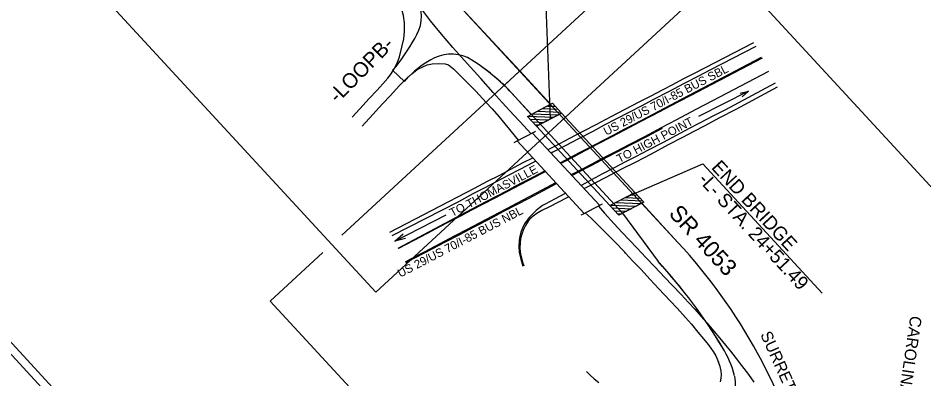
# Model space of a CAD drawing. Extents: x 1695041 to 1706254, y 786537 to 798223.
# Drawn here: x 1702539 to 1704183, y 794568 to 795222 of the extents above; entities that cross this region are included whole.
import ezdxf

# ---------------------------------------------------------------- set-up
doc = ezdxf.new("R2010")
doc.units = 0
for name, color, linetype in [('Default', 7, 'Continuous'), ('Old_Level_3', 7, 'Continuous'), ('Old_Level_4', 7, 'Continuous'), ('Old_Level_47', 7, 'Continuous'), ('Prop Approach Slab', 7, 'Continuous'), ('Prop EOT', 7, 'Continuous'), ('Prop Roadway Bridge', 7, 'Continuous'), ('Sheet Data Field CELL', 7, 'Continuous'), ('Sheet Title CELL', 7, 'Continuous')]:
    doc.layers.add(name, color=color, linetype=linetype)

msp = doc.modelspace()

# ---------------------------------------------------------------- linework, layer by layer
at = {"layer": 'Default'}
for p, q in [((1703449.8, 795126.4), (1703259.9, 795332.1)), ((1703225.7, 795134.5), (1703218.7, 795127.9)), ((1703218.7, 795127.9), (1703240.5, 795107.5)), ((1703421.5, 795100.2), (1703449.8, 795126.4)), ((1703449.8, 795126.4), (1703421.5, 795100.2)), ((1703505.8, 795065.8), (1703449.8, 795126.4)), ((1703240.5, 795107.5), (1703248.1, 795115.5)), ((1703435.6, 795085.8), (1703470.9, 795047.5)), ((1703865.4, 795089.6), (1703774.5, 795043.5)), ((1703505.8, 795065.8), (1703505.8, 795065.8)), ((1703470.9, 795047.5), (1703470.9, 795047.5)), ((1703470.9, 795047.5), (1703470.9, 795047.5)), ((1703671.5, 794886.3), (1703636.6, 794868)), ((1703671.5, 794886.3), (1703671.5, 794886.3)), ((1703671.5, 794886.3), (1703671.5, 794886.3)), ((1703671.5, 794886.3), (1703671.5, 794886.3)), ((1703671.5, 794886.3), (1703671.5, 794886.3)), ((1703671.5, 794886.3), (1703671.5, 794886.3)), ((1703223.4, 794817.6), (1703316.4, 794865)), ((1703636.6, 794868), (1703636.6, 794868)), ((1703636.6, 794868), (1703636.6, 794868)), ((1703636.6, 794868), (1703636.6, 794868)), ((1703636.6, 794868), (1703636.6, 794868)), ((1703636.6, 794868), (1703636.6, 794868)), ((1703636.6, 794868), (1703701.1, 794780.4))]:
    msp.add_line(p, q, dxfattribs=at)
for points in [[(1702347.2, 796012.7), (1702159.6, 795839.5), (1703188.6, 794724.8), (1703925.1, 795404.6), (1702896.1, 796519.3), (1702395.5, 796057.2)], [(1703666.7, 795326.6), (1703127, 794828.4)], [(1704247.3, 793859.6), (1704746.6, 794320.4), (1703838.4, 795304.4)], [(1703850.1, 795086.1), (1703865.4, 795089.6), (1703853.5, 795079.3)], [(1703470.9, 795047.5), (1703488.5, 795056.8), (1703505.8, 795065.8)], [(1703737.1, 794815.1), (1703671.5, 794886.3), (1703671.5, 794886.3)], [(1703242.6, 794822.1), (1703223.4, 794817.6), (1703238.3, 794830.5)], [(1703092.7, 794796.8), (1702997.1, 794708.5), (1703792.4, 793846.8)]]:
    msp.add_lwpolyline(points, dxfattribs=at)
for centre, radius, start, end in [((1703201.5, 795225.4), 70, 332.0106, 28.6224), ((1702910.1, 795380.3), 400, 322.0902, 332.0106), ((1703325.6, 795087), 70, 57.7993, 115.717), ((1703364.7, 795005.9), 160, 115.717, 136.7565), ((1703171.1, 794841.6), 360, 45.9217, 57.7993), ((1703171.1, 794841.6), 360, 42.7091, 45.9217), ((1702989.1, 794124.6), 1018, 14.7589, 42.7091), ((1702989.1, 794124.6), 968, 31.1029, 42.644), ((1703646.7, 794521.4), 200, 14.8969, 31.1029), ((1703791.7, 794559.9), 50, 277.9887, 14.8969)]:
    msp.add_arc(centre, radius, start, end, dxfattribs=at)
at = {"layer": 'Old_Level_3'}
for points in [[(1703145.6, 795042.7), (1703159.4, 795057.7), (1703176.4, 795076.1), (1703190.4, 795091.1), (1703201.5, 795103.1), (1703210.6, 795113.4), (1703216.4, 795121.4), (1703222, 795130.2), (1703227.5, 795140.7), (1703231.4, 795152.1), (1703236.1, 795169.3), (1703239.6, 795184.4), (1703240.7, 795197.8), (1703240.8, 795213.5), (1703238.9, 795226.9), (1703235.9, 795237.7), (1703230.6, 795251.2), (1703223.9, 795265.8), (1703215.6, 795279.8), (1703203.6, 795298.5), (1703197.6, 795306.6)], [(1703418.2, 795069.3), (1703401.7, 795087.5), (1703379, 795112.6), (1703354.2, 795139.9), (1703328.7, 795168.8), (1703308, 795193), (1703288.1, 795217.4), (1703271.7, 795238.9)], [(1703641.3, 795056.9), (1703666.7, 795070.3), (1703688.3, 795081.2), (1703708.9, 795091.9), (1703727.9, 795102), (1703746.4, 795111.8), (1703764.4, 795120.9), (1703786.8, 795132.8), (1703874.8, 795177.9)], [(1703878.3, 795171), (1703796.3, 795128.6), (1703774.5, 795117.1), (1703748.6, 795103.5), (1703720.1, 795088.7), (1703691.4, 795073.7), (1703670.1, 795062.4), (1703649.1, 795051.6), (1703624.3, 795038.9)], [(1703163.8, 795025.9), (1703183.4, 795047.6), (1703201, 795066.7), (1703215, 795081.9), (1703231.1, 795099.2), (1703243.7, 795111.8), (1703254, 795121.4), (1703264, 795128.9), (1703273.7, 795134.1), (1703281.8, 795137.4), (1703290.8, 795139.5), (1703302.6, 795139.6), (1703314.3, 795139.5), (1703320.8, 795137.4), (1703329.8, 795130.2), (1703351.4, 795108.4), (1703369.9, 795089.4), (1703388.8, 795069.2), (1703399.7, 795057.6)], [(1703889.7, 795149.3), (1703812.6, 795109.1), (1703784.4, 795094.5), (1703761.4, 795082.3), (1703736.8, 795069.6), (1703713.8, 795057.6), (1703690.6, 795045.5), (1703666.3, 795032.6), (1703639.9, 795018.9)], [(1703657.6, 795030.1), (1703681.7, 795042.7), (1703702.3, 795053.4), (1703723.9, 795064.8), (1703744.8, 795075.7), (1703768.9, 795088.3), (1703795.5, 795102.3), (1703888.7, 795151.1)], [(1703553.8, 794943.6), (1703580.2, 794957.3), (1703601.6, 794968.7), (1703625.3, 794980.9), (1703649.6, 794993.3), (1703676.8, 795007.7), (1703707.5, 795023.6), (1703735.3, 795038.4), (1703770, 795057), (1703800.1, 795072.9), (1703901.8, 795126.2)], [(1703917.4, 795097), (1703842.2, 795056.7), (1703811.3, 795040.6), (1703785.7, 795027), (1703765.6, 795016.7), (1703745.2, 795005.7), (1703719, 794992.1), (1703688.3, 794975.5), (1703660.8, 794960.9), (1703634.4, 794948.1)], [(1703913.6, 795104.1), (1703821.9, 795055.4), (1703801.4, 795044.9), (1703775.9, 795031.5), (1703757.6, 795021.8), (1703733.6, 795009.3), (1703710.1, 794996.8), (1703682.9, 794982.6)], [(1703399.7, 795057.6), (1703412, 795043.8), (1703423, 795030.3), (1703431.4, 795020), (1703439.3, 795010.5), (1703447.2, 795001)], [(1703418.2, 795069.3), (1703438.9, 795046.4), (1703449.8, 795034.7), (1703464.1, 795019.5), (1703470.3, 795012.7)], [(1703501.5, 794983.8), (1703514.6, 794990.7), (1703539.7, 795003.6), (1703566, 795017.5), (1703588.8, 795029.4), (1703616.1, 795043.6), (1703641.3, 795056.9)], [(1703624.3, 795038.9), (1703603, 795027.7), (1703582.4, 795016.7), (1703556.3, 795003), (1703532.1, 794990.5), (1703509.9, 794978.7), (1703507.2, 794977.3)], [(1703523.1, 794959.7), (1703533.6, 794965.2), (1703558.3, 794978.2), (1703576.3, 794987.5), (1703601.7, 795000.9), (1703621.7, 795011.2), (1703639.2, 795020.8), (1703657.6, 795030.1)], [(1703639.9, 795018.9), (1703616.1, 795006.3), (1703592.5, 794994.1), (1703568, 794981.2), (1703547.9, 794970.6), (1703526.7, 794959.8), (1703524.1, 794958.5)], [(1703544.8, 794936.7), (1703553.5, 794941.3), (1703580.5, 794955.6), (1703606.6, 794969.1), (1703627, 794979.6), (1703654.7, 794994.2), (1703680.4, 795007.6), (1703709.1, 795022.8)], [(1703682.9, 794982.6), (1703659.8, 794970.5), (1703641.8, 794961.2), (1703621.4, 794950.4), (1703600.4, 794939.5), (1703580.4, 794929), (1703562.3, 794919.2), (1703561.5, 794918.8)], [(1703214.3, 794834.1), (1703367.7, 794913.7), (1703391.2, 794926.1), (1703412.4, 794936.9), (1703432.7, 794947.8), (1703456.1, 794960.1), (1703473.4, 794968.9)], [(1703474.4, 794960.4), (1703450.3, 794947.8), (1703429, 794936.5), (1703407.2, 794925.2), (1703385.6, 794913.9), (1703364.9, 794903.2), (1703338.5, 794889.1), (1703217.9, 794827.1)], [(1703479.1, 794962.8), (1703474.4, 794960.4)], [(1703229.3, 794805), (1703342.8, 794865.2), (1703363.4, 794876), (1703386.5, 794888), (1703407.9, 794899.3), (1703426.2, 794909), (1703441.8, 794917.1), (1703457, 794925.2), (1703474.8, 794934.4), (1703495.4, 794945.1)], [(1703497.1, 794943.8), (1703490.2, 794940.1), (1703467.2, 794928.3), (1703449.5, 794919), (1703427.5, 794907.9), (1703404.5, 794895.8), (1703383.5, 794884.8), (1703361.2, 794872.9), (1703343.6, 794863.7), (1703320.8, 794851.9), (1703304.3, 794843.3), (1703281.9, 794831.2), (1703257.8, 794818.4), (1703229.9, 794803.9)], [(1703543.4, 794938.2), (1703553.8, 794943.6)], [(1703634.4, 794948.1), (1703605, 794932.2), (1703570.1, 794914.4), (1703566.9, 794912.8)], [(1703242.3, 794780), (1703252.3, 794785.2), (1703276.8, 794798.4), (1703304.5, 794812.9), (1703331.5, 794827.1), (1703354.8, 794839.3), (1703376.6, 794850.6), (1703401.3, 794863.6), (1703426.4, 794876.6), (1703445.9, 794887), (1703466.1, 794897.8), (1703490.6, 794910.9), (1703515.2, 794923.7)], [(1703445.6, 794884.8), (1703465.5, 794895.2), (1703493.2, 794909.7), (1703516.8, 794921.9)], [(1703538.8, 794898), (1703535.5, 794896.3), (1703503.7, 794880), (1703489.9, 794873.3), (1703480.8, 794867.9), (1703474.4, 794863.1), (1703469.9, 794859.2), (1703465.2, 794853.8), (1703460.5, 794846.2), (1703456.8, 794838.5), (1703453.5, 794830.1), (1703451.5, 794822.3), (1703450.4, 794814), (1703450.1, 794806.1), (1703450.9, 794797.5), (1703452.1, 794791.3), (1703453.4, 794784.7), (1703454.9, 794779.5), (1703457.4, 794772.5)], [(1703533.3, 794904.4), (1703531.3, 794903.3), (1703514.4, 794894.4), (1703495.9, 794884.6)], [(1703243.3, 794778.4), (1703248, 794780.9), (1703274.6, 794794.9), (1703292.4, 794804.1), (1703315.2, 794816.2), (1703341, 794829.7), (1703368.4, 794844.1), (1703395.3, 794858.1), (1703419.9, 794871.1), (1703445.6, 794884.8)], [(1703495.9, 794884.6), (1703491.4, 794882.2), (1703485.9, 794878), (1703480, 794873.1), (1703473.4, 794867.1), (1703467.5, 794861.3), (1703463.2, 794855.6), (1703458.8, 794849.1), (1703454.6, 794841.2), (1703451.9, 794834.1), (1703450, 794826.7), (1703448.6, 794818.4), (1703448.3, 794807.9), (1703449, 794797.8), (1703451.8, 794784.6), (1703455.6, 794771.9)], [(1703592.7, 794881), (1703604, 794868.1), (1703621.2, 794849.1), (1703636.1, 794833.2), (1703649.1, 794819.4), (1703663.1, 794804.9), (1703678.7, 794788.1), (1703695.1, 794771.1), (1703712.9, 794752.3), (1703727.4, 794737), (1703742.7, 794720.6), (1703756.4, 794706.3), (1703767.6, 794693.8), (1703779.2, 794680.9), (1703789.6, 794669.2), (1703802, 794654.4), (1703812.3, 794642.3), (1703823.3, 794628.9), (1703832.6, 794617.6), (1703842.9, 794604.6), (1703852.7, 794591.9), (1703864.9, 794575.6), (1703875.1, 794561.5)], [(1703641.7, 794796), (1703640.5, 794797.3), (1703621.6, 794816.8), (1703606.4, 794832.6), (1703591.3, 794847.6), (1703579.8, 794859.4), (1703568.9, 794869)], [(1703641.7, 794796), (1703655.4, 794781.3), (1703669.5, 794766.4), (1703686.6, 794748), (1703702.3, 794731.2), (1703722.2, 794710.1), (1703735.4, 794695.8), (1703750.8, 794678.8), (1703761.5, 794666.8), (1703773.1, 794652.4), (1703783.3, 794640.2), (1703791.8, 794630), (1703796.8, 794623.6), (1703801.1, 794617.2), (1703805.9, 794609.5), (1703810.9, 794598)], [(1703814.1, 794562), (1703815.5, 794568.8), (1703815.9, 794574.9), (1703815.4, 794582.3), (1703813.8, 794590.2), (1703810.9, 794598)], [(1703570.9, 794580.8), (1703577.8, 794574.1), (1703584.9, 794567.9), (1703593.7, 794561)]]:
    msp.add_lwpolyline(points, dxfattribs=at)
at = {"layer": 'Old_Level_4'}
for points in [[(1703439.9, 794996.6), (1703444.2, 794999), (1703476.5, 795015.7), (1703478.7, 795016.8)], [(1703594.4, 794882.7), (1703473.3, 795013.7)], [(1703445.1, 794999.6), (1703566.6, 794867.9)], [(1703561.4, 794865.4), (1703564.2, 794866.6), (1703597.7, 794884.2), (1703600.4, 794885.5)]]:
    msp.add_lwpolyline(points, dxfattribs=at)
at = {"layer": 'Prop Approach Slab'}
for p, q in [((1703464, 795043.9), (1703509.4, 795067.7)), ((1703464, 795043.9), (1703509.4, 795067.7)), ((1703491.1, 795058.1), (1703519.4, 795057)), ((1703500, 795062.7), (1703514.6, 795062.2)), ((1703509.4, 795067.7), (1703525.8, 795050)), ((1703480.4, 795026.2), (1703464, 795043.9)), ((1703464.5, 795044.1), (1703511.1, 795042.3)), ((1703473.3, 795048.8), (1703520, 795046.9)), ((1703480.4, 795026.2), (1703524.4, 795049.3)), ((1703482.2, 795053.4), (1703524.2, 795051.8)), ((1703468.6, 795039), (1703502.3, 795037.6)), ((1703473.4, 795033.8), (1703493.4, 795033)), ((1703478.2, 795028.6), (1703484.5, 795028.3)), ((1703641.5, 794896.9), (1703668.1, 794895.8)), ((1703650.4, 794901.5), (1703663.3, 794901)), ((1703658.8, 794905.9), (1703675.2, 794888.2)), ((1703613.3, 794882.2), (1703629.7, 794864.5)), ((1703614.8, 794882.9), (1703661.5, 794881.1)), ((1703617.3, 794877.8), (1703652.6, 794876.4)), ((1703623.7, 794887.6), (1703670.4, 794885.7)), ((1703675.2, 794888.2), (1703629.7, 794864.5)), ((1703632.6, 794892.2), (1703672.9, 794890.6)), ((1703622.1, 794872.6), (1703643.7, 794871.8)), ((1703626.9, 794867.5), (1703634.8, 794867.1))]:
    msp.add_line(p, q, dxfattribs=at)
for points in [[(1703509.4, 795067.7), (1703525.8, 795050), (1703480.4, 795026.2), (1703464, 795043.9)], [(1703658.8, 794905.9), (1703675.2, 794888.2), (1703629.7, 794864.5), (1703613.3, 794882.2)]]:
    msp.add_lwpolyline(points, close=True, dxfattribs=at)
at = {"layer": 'Prop EOT'}
for p, q in [((1703259.9, 795332.1), (1703737.1, 794815.1)), ((1703218.7, 795127.9), (1703225.7, 795134.5)), ((1703218.7, 795127.9), (1703240.5, 795107.5)), ((1703240.5, 795107.5), (1703248.1, 795115.5)), ((1703419, 795103.8), (1703636.6, 794868)), ((1703636.6, 794868), (1703701, 794780.6))]:
    msp.add_line(p, q, dxfattribs=at)
for centre, radius, start, end in [((1703201.5, 795225.4), 70, 332.0106, 28.6224), ((1702910.1, 795380.3), 400, 322.0902, 332.0106), ((1703325.6, 795087), 70, 57.7993, 115.717), ((1703364.7, 795005.9), 160, 115.717, 136.7565), ((1703171.1, 794841.6), 360, 42.7091, 57.7993), ((1702989.1, 794124.6), 1018, 14.7589, 42.7091), ((1702989.1, 794124.6), 968, 31.1029, 42.6557), ((1703646.7, 794521.4), 200, 14.8969, 31.1029), ((1703791.7, 794559.9), 50, 277.9887, 14.8969)]:
    msp.add_arc(centre, radius, start, end, dxfattribs=at)
at = {"layer": 'Prop Roadway Bridge'}
for p, q in [((1703480.4, 795026.2), (1703525.8, 795050)), ((1703525.8, 795050), (1703658.8, 794905.9)), ((1703480.4, 795026.2), (1703613.3, 794882.2)), ((1703613.3, 794882.2), (1703658.8, 794905.9))]:
    msp.add_line(p, q, dxfattribs=at)
at = {"layer": 'Sheet Title CELL'}
for p, q in [((1701348.1, 795910.6), (1704237.6, 792780.3)), ((1703505.6, 795039.4), (1703493.6, 795366.4)), ((1702028.9, 795150.9), (1702802.2, 794313.2)), ((1703638.6, 794895.4), (1703782, 794958.1)), ((1703782, 794958.1), (1703998.7, 794723.3))]:
    msp.add_line(p, q, dxfattribs=at)

# ---------------------------------------------------------------- texts
at = {"layer": 'Default'}
for s, rotation, p in [('TO HIGH POINT ', 27.5467, (1703630.7, 794959.1)), ('TO THOMASVILLE', 27.5803, (1703327.5, 794861.1))]:
    msp.add_text(s, height=15.259, rotation=rotation, dxfattribs=at).set_placement(p)
at = {"layer": 'Old_Level_47'}
for s, p in [('END BRIDGE', (1703796.3, 794950.2)), ('-L- STA. 24+51.49', (1703772.2, 794928))]:
    msp.add_text(s, height=25, rotation=312.7091, dxfattribs=at).set_placement(p)
at = {"layer": 'Sheet Data Field CELL'}
for s, p in [('REPLACEMENT OF BRIDGE 77 ON SR 4053 (SURRETT DR)', (1704034.8, 796009.4)), ('GRADING, DRAINAGE, PAVING, STRUCTURE    ', (1703996.4, 795754.4))]:
    msp.add_text(s, height=37.5, rotation=312.7091, dxfattribs=at).set_placement(p)
at = {"layer": 'Sheet Title CELL'}
for s, height, rotation, p in [('-LOOPB-', 27, 45.445, (1703119.3, 795066.8)), ('US 29/US 70/I-85 BUS SBL', 15.259, 27.5803, (1703606.9, 795008.7)), ('US 29/US 70/I-85 BUS NBL', 15.259, 27.5467, (1703233.1, 794751.1)), ('SR 4053', 30, 312.7091, (1703718.8, 794866.4)), ('CAROLINA NORTHWESTERN R/R', 21.157, 261.6993, (1704159, 794682.9)), ('SURRETT DR', 21.16, 294.2459, (1703886.1, 794648.3))]:
    msp.add_text(s, height=height, rotation=rotation, dxfattribs=at).set_placement(p)

doc.saveas('drawing.dxf')
